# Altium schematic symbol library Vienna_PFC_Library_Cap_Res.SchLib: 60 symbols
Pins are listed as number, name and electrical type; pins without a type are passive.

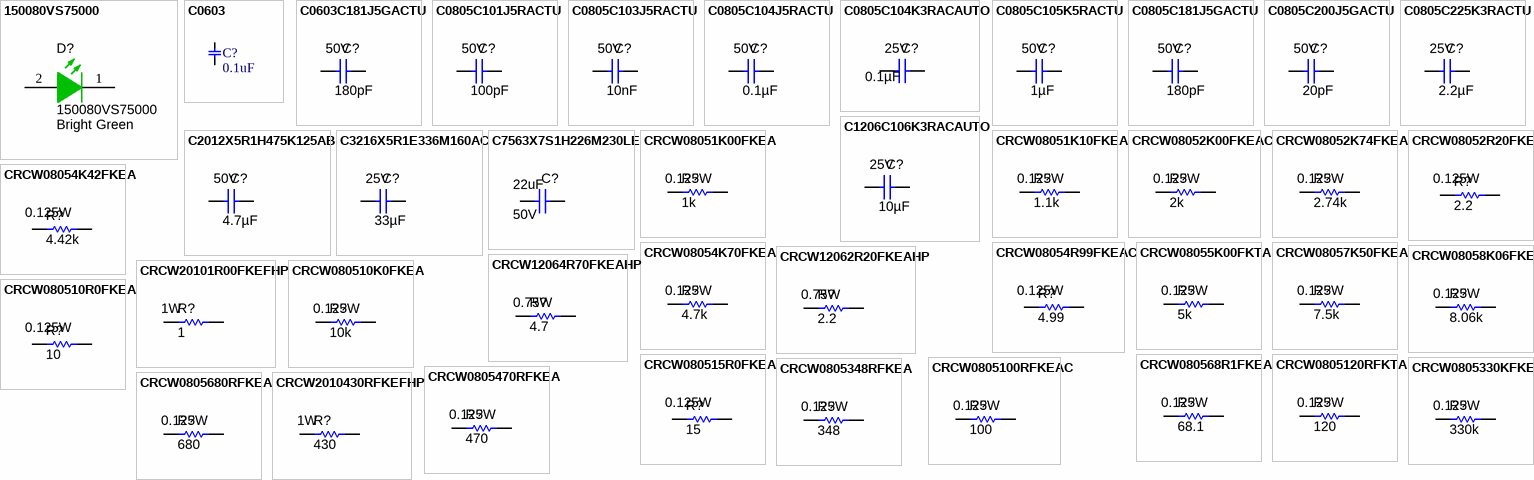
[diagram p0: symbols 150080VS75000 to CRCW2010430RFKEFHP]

## 150080VS75000
designator D?  value Bright Green
LED, Bright Green, SMD; Manufacturer: Wurth Elektronik; SymbolCreator: Altium; Type: AlInGaP; Vf_V: 2; Value2: 2V; Io_A: 0.02; Vr_V: 5; Tjmax_C: 85; Power_TotalModule: 0.072; Value1: 0.072W; Angle: 140; U/M: EA
footprint WL-SMCW_Green_0805 (SMD, 2-Leads, Body 2x1.25mm)
pins: 1 K, 2 A

## C0603
designator C?, comment 0.1uF
footprint C0603
pins: 1, 2

## C0603C181J5GACTU
designator C?  VDC_V: 50V  ValueDisplayed: 180pF  (hidden comment: C0603C181J5GACTU)
CAP, CERM, 180 pF, 50 V, +/- 5%, C0G/NP0, 0603; Manufacturer: Kemet; Polarized: N; CompType: Capacitor; Value: 180pF; U/M: EA; Cap_F: 0.00000000018; Tolerance_%: 5; Value1: Unknown; TaMin_C: -55; TaMax_C: 125; Cap_Case: 0603; SizeArea_mm2: 1.28; SizeAreaWB_mm2: 4.68; SizeX_mm: 1.6; SizeY_mm: 0.8; SizeZ_mm: 1; AEC Category: Q200
signal-integrity model Cap
simulation model Cap
footprint 0603 (0603 from SM-752 data)
footprint 0603M
footprint 0603L
footprint 0603_HV
footprint 0603S
pins: 1, 2

## C0805C101J5RACTU
designator C?  VDC_V: 50V  ValueDisplayed: 100pF  (hidden comment: C0805C101J5RACTU)
CAP, CERM, 100 pF, 50 V, +/- 5%, X7R, 0805; Manufacturer: Kemet; CompType: Capacitor; Tolerance_%: 5; TaMin_C: -55; TaMax_C: 125; Cap_Case: 0805; AEC Category: Q200
signal-integrity model Cap
simulation model Cap
footprint 0805_HV (0805 with 30mil clearance between pads)
footprint 0805_HV1
footprint 0805
footprint 0805M
footprint 0805L
pins: 1, 2

## C0805C103J5RACTU
designator C?  VDC_V: 50V  ValueDisplayed: 10nF  (hidden comment: C0805C103J5RACTU)
CAP, CERM, 10 nF, 50 V, +/- 5%, X7R, 0805; Manufacturer: Kemet; CompType: Capacitor; Tolerance_%: 5; TaMin_C: -55; TaMax_C: 125; Cap_Case: 0805; AEC Category: Q200
signal-integrity model Cap
simulation model Cap
footprint 0805_HV (0805 with 30mil clearance between pads)
footprint 0805_HV1
footprint 0805
footprint 0805M
footprint 0805L
pins: 1, 2

## C0805C104J5RACTU
designator C?  VDC_V: 50V  ValueDisplayed: 0.1µF  (hidden comment: C0805C104J5RACTU)
CAP, CERM, 0.1 µF, 50 V, +/- 5%, X7R, 0805; Manufacturer: Kemet; CompType: Capacitor; Tolerance_%: 5; TaMin_C: -55; TaMax_C: 125; Cap_Case: 0805; AEC Category: Q200
signal-integrity model Cap
simulation model Cap
footprint 0805_HV (0805 with 30mil clearance between pads)
footprint 0805_HV1
footprint 0805
footprint 0805M
footprint 0805L
pins: 1, 2

## C0805C104K3RACAUTO
designator C?  VDC_V: 25V  ValueDisplayed: 0.1µF  (hidden comment: C0805C104K3RACAUTO)
CAP, CERM, 0.1 µF, 25 V, +/- 10%, X7R, 0805; Manufacturer: Kemet; Polarized: N; CompType: Capacitor; Value: 0.1uF; U/M: EA; Cap_F: 0.0000001; Tolerance_%: 10; ESR_ohm: 0.064; Value1: 0.064 ohm; IRMS_A: 1.64; TaMin_C: -55; TaMax_C: 125; Cap_Case: 0805; AEC Category: Q200
signal-integrity model Cap
simulation model Cap
footprint 0805_HV
footprint 0805_HV1
footprint 0805
footprint 0805M
footprint 0805L
pins: 1, 2

## C0805C105K5RACTU
designator C?  VDC_V: 50V  ValueDisplayed: 1µF  (hidden comment: C0805C105K5RACTU)
CAP, CERM, 1 µF, 50 V, +/- 5%, X7R, 0805; Manufacturer: Kemet; CompType: Capacitor; Tolerance_%: 10; TaMin_C: -55; TaMax_C: 125; Cap_Case: 0805; AEC Category: Q200
signal-integrity model Cap
simulation model Cap
footprint 0805_HV (0805 with 30mil clearance between pads)
footprint 0805_HV1
footprint 0805
footprint 0805M
footprint 0805L
pins: 1, 2

## C0805C181J5GACTU
designator C?  VDC_V: 50V  ValueDisplayed: 180pF  (hidden comment: C0805C181J5GACTU)
CAP, CERM, 180 pF, 50 V, +/- 5%, X7R, 0805; Manufacturer: Kemet; CompType: Capacitor; Tolerance_%: 5; TaMin_C: -55; TaMax_C: 125; Cap_Case: 0805; AEC Category: Q200
signal-integrity model Cap
simulation model Cap
footprint 0805_HV (0805 with 30mil clearance between pads)
footprint 0805_HV1
footprint 0805
footprint 0805M
footprint 0805L
pins: 1, 2

## C0805C200J5GACTU
designator C?, comment VDC_V: 50V  ValueDisplayed: 20pF  (hidden comment: C0805C101J5RACTU)
CAP, CERM, 20 pF, 50 V, +/- 5%, X7R, 0805; Manufacturer: Kemet; CompType: Capacitor; Tolerance_%: 5; TaMin_C: -55; TaMax_C: 125; Cap_Case: 0805; AEC Category: Q200
signal-integrity model Cap
simulation model Cap
footprint 0805_HV (0805 with 30mil clearance between pads)
footprint 0805_HV1
footprint 0805
footprint 0805M
footprint 0805L
pins: 1, 2

## C0805C225K3RACTU
designator C?  VDC_V: 25V  ValueDisplayed: 2.2µF  (hidden comment: C0805C225K3RACTU)
CAP, CERM, 2.2 µF, 25 V, +/- 5%, X7R, 0805; Manufacturer: Kemet; CompType: Capacitor; Tolerance_%: 10; TaMin_C: -55; TaMax_C: 125; Cap_Case: 0805; AEC Category: Q200
signal-integrity model Cap
simulation model Cap
footprint 0805_HV (0805 with 30mil clearance between pads)
footprint 0805_HV1
footprint 0805
footprint 0805M
footprint 0805L
pins: 1, 2

## C1206C106K3RACAUTO
designator C?  VDC_V: 25V  ValueDisplayed: 10µF  (hidden comment: C1206C106K3RACAUTO)
CAP, CERM, 10 µF, 25 V, +/- 10%, X7R, 1206_190; Manufacturer: Kemet; Polarized: N; CompType: Capacitor; Value: 10uF; U/M: EA; Cap_F: 0.00001; Tolerance_%: 10; Value1: Unknown; TaMin_C: -55; TaMax_C: 125; Cap_Case: 1206; AEC Category: Q200
signal-integrity model Cap
simulation model Cap
footprint 1206_190
footprint 1206_190M
footprint 1206_190L
pins: 1, 2

## C2012X5R1H475K125AB
designator C?  VDC_V: 50V  ValueDisplayed: 4.7µF  (hidden comment: C2012X5R1H475K125AB)
CAP, CERM, 4.7 µF, 50 V, +/- 10%, X5R, 0805; Manufacturer: TDK; Polarized: N; CompType: Capacitor; Value: 4.7uF; U/M: EA; Cap_F: 0.0000047; Tolerance_%: 10; Value1: Unknown; TaMin_C: -55; TaMax_C: 85; Cap_Case: 0805; AEC Category: Q200
signal-integrity model Cap
simulation model Cap
footprint 0805_HV (0805 with 30mil clearance between pads)
pins: 1, 2

## C3216X5R1E336M160AC
designator C?  VDC_V: 25V  ValueDisplayed: 33µF  (hidden comment: C3216X5R1E336M160AC)
CAP, CERM, 33 µF, 25 V, +/- 20%, X5R, 1206; Manufacturer: TDK; Polarized: N; CompType: Capacitor; Value: 33uF; U/M: EA; Tolerance_%: 20; Value1: Unknown; TaMin_C: -55; TaMax_C: 85; Cap_Case: 1206; AEC Category: Q200
signal-integrity model Cap
simulation model Cap
footprint 1206_190
pins: 1, 2

## C7563X7S1H226M230LE
designator C?  value 22uF  VDC_V: 50V  (hidden comment: C7563X7S1H226M230LE)
CAP, CERM, 22 µF, 50V, +/- 20%, X7S, 3525; AEC Category: Q200; ValueDisplayed: 22µF
signal-integrity model Cap
simulation model Cap
footprint 3025 (Chip Resistor, Body 7.5*6.3mm, IPC Medium Density)
pins: 1, 2

## CRCW08051K00FKEA
designator R?  Value2: 0.125W  ValueDisplayed: 1k  (hidden comment: CRCW08051K00FKEA)
RES, 1 k, 1%, 0.125 W, 0805; Manufacturer: Vishay-Dale; CompType: Resistor; Value: 1k; Value_Code: 1kR; Tolerance_%: 1; Power_W: 0.125; VDC_V: 150; TempCo: 100 ppm/C; EIA_Code: E96; U/M: EA; AEC Category: Q200
signal-integrity model Resistor
simulation model Resistor
footprint 0805_HV (0805 with 30mil clearance between pads)
footprint 0805_HV1
footprint 0805
footprint 0805M
pins: 1, 2

## CRCW08051K10FKEA
designator R?  Value2: 0.125W  ValueDisplayed: 1.1k  (hidden comment: CRCW08051K10FKEA)
RES, 1.1K, 1%, 0.125 W, 0805; Manufacturer: Vishay-Dale; CompType: Resistor; Tolerance_%: 1; Power_W: 0.125; VDC_V: 150; TempCo: 100 ppm/C; EIA_Code: E96; U/M: EA; AEC Category: Q200
signal-integrity model Resistor
simulation model Resistor
footprint 0805_HV (0805 with 30mil clearance between pads)
footprint 0805_HV1
footprint 0805
footprint 0805M
pins: 1, 2

## CRCW08052K00FKEAC
designator R?  Value2: 0.125W  ValueDisplayed: 2k  (hidden comment: CRCW08052K00FKEAC)
RES, 2K, 1%, 0.125 W, 0805; Manufacturer: Vishay-Dale; CompType: Resistor; Value: 348; Tolerance_%: 1; Power_W: 0.125; VDC_V: 150; TempCo: 100 ppm/C; EIA_Code: E96; U/M: EA; AEC Category: Q200
signal-integrity model Resistor
simulation model Resistor
footprint 0805_HV (0805 with 30mil clearance between pads)
footprint 0805_HV1
footprint 0805
footprint 0805M
pins: 1, 2

## CRCW08052K74FKEA
designator R?  Value2: 0.125W  ValueDisplayed: 2.74k  (hidden comment: CRCW08052K74FKEA)
RES, 2.74K, 1%, 0.125 W, 0805; Manufacturer: Vishay-Dale; CompType: Resistor; Res_ohm: 348; Tolerance_%: 1; Power_W: 0.125; VDC_V: 150; TempCo: 100 ppm/C; EIA_Code: E96; U/M: EA; AEC Category: Q200
signal-integrity model Resistor
simulation model Resistor
footprint 0805_HV (0805 with 30mil clearance between pads)
footprint 0805_HV1
footprint 0805
footprint 0805M
pins: 1, 2

## CRCW08052R20FKEA
designator R?  Value2: 0.125W  ValueDisplayed: 2.2  (hidden comment: CRCW08052R20FKEA)
RES, 2.2 1%, 0.125 W, 0805; Manufacturer: Vishay-Dale; CompType: Resistor; Value: 2.2; Value_Code: 2R2; Tolerance_%: 1; Power_W: 0.125; VDC_V: 150; TempCo: 100 ppm/C; SizeArea_mm2: 2.5; SizeX_mm: 2; SizeY_mm: 1.25; SizeZ_mm: 1.45; EIA_Code: E24; U/M: EA; AEC Category: Q200
signal-integrity model Resistor
simulation model Resistor
footprint 0805_HV (0805 with 30mil clearance between pads)
footprint 0805_HV1
footprint 0805
footprint 0805M
footprint 0805L
pins: 1, 2

## CRCW08054K42FKEA
designator R?  Value2: 0.125W  ValueDisplayed: 4.42k  (hidden comment: CRCW08054K42FKEA)
RES, 4.42k 1%, 0.125 W, 0805; Manufacturer: Vishay-Dale; CompType: Resistor; Value_Code: 4K42; Tolerance_%: 1; Power_W: 0.125; VDC_V: 150; TempCo: 100 ppm/C; SizeArea_mm2: 2.5; SizeX_mm: 2; SizeY_mm: 1.25; SizeZ_mm: 1.45; EIA_Code: E24; U/M: EA; AEC Category: Q200
signal-integrity model Resistor
simulation model Resistor
footprint 0805_HV (0805 with 30mil clearance between pads)
footprint 0805_HV1
footprint 0805
footprint 0805M
footprint 0805L
pins: 1, 2

## CRCW08054K70FKEA
designator R?  Value2: 0.125W  ValueDisplayed: 4.7k  (hidden comment: CRCW08054K70FKEA)
RES, 4.7K, 1%, 0.125 W, 0805; Manufacturer: Vishay-Dale; CompType: Resistor; Tolerance_%: 1; Power_W: 0.125; VDC_V: 150; TempCo: 100 ppm/C; EIA_Code: E96; U/M: EA; AEC Category: Q200
signal-integrity model Resistor
simulation model Resistor
footprint 0805_HV (0805 with 30mil clearance between pads)
footprint 0805_HV1
footprint 0805
footprint 0805M
pins: 1, 2

## CRCW08054R99FKEAC
designator R?  Value2: 0.125W  ValueDisplayed: 4.99  (hidden comment: CRCW08054R99FKEAC)
RES, 4.99 1%, 0.125 W, 0805; Manufacturer: Vishay-Dale; CompType: Resistor; Value: 4.99; Value_Code: 4R99; Tolerance_%: 1; Power_W: 0.125; VDC_V: 150; TempCo: 100 ppm/C; SizeArea_mm2: 2.5; SizeX_mm: 2; SizeY_mm: 1.25; SizeZ_mm: 1.45; EIA_Code: E24; U/M: EA; AEC Category: Q200
signal-integrity model Resistor
simulation model Resistor
footprint 0805_HV (0805 with 30mil clearance between pads)
footprint 0805_HV1
footprint 0805
footprint 0805M
footprint 0805L
pins: 1, 2

## CRCW08055K00FKTA
designator R?  Value2: 0.125W  ValueDisplayed: 5k  (hidden comment: CRCW08055K00FKTA)
RES, 5K, 1%, 0.125 W, 0805; Manufacturer: Vishay-Dale; CompType: Resistor; Tolerance_%: 1; Power_W: 0.125; VDC_V: 150; TempCo: 100 ppm/C; EIA_Code: E96; U/M: EA; AEC Category: Q200
signal-integrity model Resistor
simulation model Resistor
footprint 0805_HV (0805 with 30mil clearance between pads)
footprint 0805_HV1
footprint 0805
footprint 0805M
pins: 1, 2

## CRCW08057K50FKEA
designator R?  Value2: 0.125W  ValueDisplayed: 7.5k  (hidden comment: CRCW08057K50FKEA)
RES, 7.5K, 1%, 0.125 W, 0805; Manufacturer: Vishay-Dale; CompType: Resistor; Value: 348; Tolerance_%: 1; Power_W: 0.125; VDC_V: 150; TempCo: 100 ppm/C; EIA_Code: E96; U/M: EA; AEC Category: Q200
signal-integrity model Resistor
simulation model Resistor
footprint 0805_HV (0805 with 30mil clearance between pads)
footprint 0805_HV1
footprint 0805
footprint 0805M
pins: 1, 2

## CRCW08058K06FKEA
designator R?  Value2: 0.125W  ValueDisplayed: 8.06k  (hidden comment: CRCW08058K06FKEA)
RES, 8.06K, 1%, 0.125 W, 0805; Manufacturer: Vishay-Dale; CompType: Resistor; Value: 348; Tolerance_%: 1; Power_W: 0.125; VDC_V: 150; TempCo: 100 ppm/C; EIA_Code: E96; U/M: EA; AEC Category: Q200
signal-integrity model Resistor
simulation model Resistor
footprint 0805_HV (0805 with 30mil clearance between pads)
footprint 0805_HV1
footprint 0805
footprint 0805M
pins: 1, 2

## CRCW12062R20FKEAHP
designator R?, comment Value2: 0.75W  ValueDisplayed: 2.2  (hidden comment: CRCW12064R70FKEAHP)
RES, 2.2, 1%, 0.75 W, 1206; Manufacturer: Vishay-Dale; CompType: Resistor; Value: 2.2; Value_Code: 2R2; Tolerance_%: 1; Power_W: 0.75; VDC_V: 200V; TempCo: 100 ppm/C; U/M: EA; AEC Category: Q200
signal-integrity model Resistor
simulation model Resistor
footprint 1206_190
footprint 0805_HV1
footprint 0805
footprint 0805M
pins: 1, 2

## CRCW12064R70FKEAHP
designator R?, comment Value2: 0.75W  ValueDisplayed: 4.7  (hidden comment: CRCW12062R20FKEAHP)
RES, 4.7, 1%, 0.75 W, 1206; Manufacturer: Vishay-Dale; CompType: Resistor; Value: 4.7; Value_Code: 4R7; Tolerance_%: 1; Power_W: 0.75; VDC_V: 200V; TempCo: 100 ppm/C; U/M: EA; AEC Category: Q200
signal-integrity model Resistor
simulation model Resistor
footprint 1206_190
footprint 0805_HV1
footprint 0805
footprint 0805M
pins: 1, 2

## CRCW20101R00FKEFHP
designator R?  Value2: 1W  ValueDisplayed: 1  (hidden comment: CRCW20101R00FKEFHP)
RES, 1, 1%, 1 W, 2010; Manufacturer: Vishay-Dale; CompType: Resistor; Value: 1; Value_Code: 1R; VDC_V: 300; TempCo: 100 ppm/C; U/M: EA; AEC Category: Q200
signal-integrity model Resistor
simulation model Resistor
footprint 2010 (Chip Capacitor, Body 5.08x2.54mm, IPC Medium Density)
footprint 0805_HV1
footprint 0805
footprint 0805M
pins: 1, 2

## CRCW080510K0FKEA
designator R?  Value2: 0.125W  ValueDisplayed: 10k  (hidden comment: CRCW080510K0FKEA)
RES, 10K, 1%, 0.125 W, 0805; Manufacturer: Vishay-Dale; CompType: Resistor; Tolerance_%: 1; Power_W: 0.125; VDC_V: 150; TempCo: 100 ppm/C; EIA_Code: E96; U/M: EA; AEC Category: Q200
signal-integrity model Resistor
simulation model Resistor
footprint 0805_HV (0805 with 30mil clearance between pads)
footprint 0805_HV1
footprint 0805
footprint 0805M
pins: 1, 2

## CRCW080510R0FKEA
designator R?, comment Value2: 0.125W  ValueDisplayed: 10  (hidden comment: CRCW080510R0JNEA)
RES, 10, 1%, 0.125 W, 0805; Manufacturer: Vishay-Dale; CompType: Resistor; Value: 10; Value_Code: 10R0; Tolerance_%: 1; Power_W: 0.125; VDC_V: 150; TempCo: 100 ppm/C; SizeArea_mm2: 2.5; SizeX_mm: 2; SizeY_mm: 1.25; SizeZ_mm: 1.45; EIA_Code: E24; U/M: EA; AEC Category: Q200
signal-integrity model Resistor
simulation model Resistor
footprint 0805_HV (0805 with 30mil clearance between pads)
footprint 0805_HV1
footprint 0805
footprint 0805M
footprint 0805L
pins: 1, 2

## CRCW080515R0FKEA
designator R?  Value2: 0.125W  ValueDisplayed: 15  (hidden comment: CRCW080515R0FKEA)
RES, 15, 1%, 0.125 W, 0805; Manufacturer: Vishay-Dale; CompType: Resistor; Value: 15; Value_Code: 15R0; Tolerance_%: 1; Power_W: 0.125; VDC_V: 150; TempCo: 100 ppm/C; SizeArea_mm2: 2.5; SizeX_mm: 2; SizeY_mm: 1.25; SizeZ_mm: 1.45; EIA_Code: E24; U/M: EA; AEC Category: Q200
signal-integrity model Resistor
simulation model Resistor
footprint 0805_HV (0805 with 30mil clearance between pads)
footprint 0805_HV1
footprint 0805
footprint 0805M
footprint 0805L
pins: 1, 2

## CRCW080568R1FKEA
designator R?  Value2: 0.125W  ValueDisplayed: 68.1  (hidden comment: CRCW080568R1FKEA)
RES, 68.1, 1%, 0.125 W, 0805; Manufacturer: Vishay-Dale; CompType: Resistor; Value: 348; Value_Code: 68R1; Tolerance_%: 1; Power_W: 0.125; VDC_V: 150; TempCo: 100 ppm/C; EIA_Code: E96; U/M: EA; AEC Category: Q200
signal-integrity model Resistor
simulation model Resistor
footprint 0805_HV (0805 with 30mil clearance between pads)
footprint 0805_HV1
footprint 0805
footprint 0805M
pins: 1, 2

## CRCW0805100RFKEAC
designator R?  Value2: 0.125W  ValueDisplayed: 100  (hidden comment: CRCW0805100RFKEAC)
RES, 100, 1%, 0.125 W, 0805; Manufacturer: Vishay-Dale; CompType: Resistor; Value: 100; Value_Code: 100R; Tolerance_%: 1; Power_W: 0.125; VDC_V: 150; TempCo: 100 ppm/C; EIA_Code: E96; U/M: EA; AEC Category: Q200
signal-integrity model Resistor
simulation model Resistor
footprint 0805_HV (0805 with 30mil clearance between pads)
footprint 0805_HV1
footprint 0805
footprint 0805M
pins: 1, 2

## CRCW0805120RFKTA
designator R?  Value2: 0.125W  ValueDisplayed: 120  (hidden comment: CRCW0805120RFKTA)
RES, 120, 1%, 0.125 W, 0805; Manufacturer: Vishay-Dale; CompType: Resistor; Value: 120; Value_Code: 120R; Tolerance_%: 1; Power_W: 0.125; VDC_V: 150; TempCo: 100 ppm/C; EIA_Code: E96; U/M: EA; AEC Category: Q200
signal-integrity model Resistor
simulation model Resistor
footprint 0805_HV (0805 with 30mil clearance between pads)
footprint 0805_HV1
footprint 0805
footprint 0805M
pins: 1, 2

## CRCW0805330KFKEA
designator R?  Value2: 0.125W  ValueDisplayed: 330k  (hidden comment: CRCW0805330KFKEA)
RES, 330 k, 1%, 0.125 W, 0805; Manufacturer: Vishay-Dale; CompType: Resistor; Value: 330k; Value_Code: 330kR; Tolerance_%: 1; Power_W: 0.125; VDC_V: 150; TempCo: 100 ppm/C; EIA_Code: E96; U/M: EA; AEC Category: Q200
signal-integrity model Resistor
simulation model Resistor
footprint 0805_HV (0805 with 30mil clearance between pads)
footprint 0805_HV1
footprint 0805
footprint 0805M
pins: 1, 2

## CRCW0805348RFKEA
designator R?  Value2: 0.125W  ValueDisplayed: 348  (hidden comment: CRCW0805348RFKEA)
RES, 348, 1%, 0.125 W, 0805; Manufacturer: Vishay-Dale; CompType: Resistor; Value: 348; Value_Code: 348R; Tolerance_%: 1; Power_W: 0.125; VDC_V: 150; TempCo: 100 ppm/C; EIA_Code: E96; U/M: EA; AEC Category: Q200
signal-integrity model Resistor
simulation model Resistor
footprint 0805_HV (0805 with 30mil clearance between pads)
footprint 0805_HV1
footprint 0805
footprint 0805M
pins: 1, 2

## CRCW0805470RFKEA
designator R?  Value2: 0.125W  ValueDisplayed: 470  (hidden comment: CRCW0805470RFKEA)
RES, 470, 1%, 0.125 W, 0805; Manufacturer: Vishay-Dale; CompType: Resistor; Value: 470; Value_Code: 470R; Tolerance_%: 1; Power_W: 0.125; VDC_V: 150; TempCo: 100 ppm/C; U/M: EA; AEC Category: Q200
signal-integrity model Resistor
simulation model Resistor
footprint 0805_HV (0805 with 30mil clearance between pads)
footprint 0805_HV1
footprint 0805
footprint 0805M
pins: 1, 2

## CRCW0805680RFKEA
designator R?  Value2: 0.125W  ValueDisplayed: 680  (hidden comment: CRCW0805680RFKEA)
RES, 680, 1%, 0.125 W, 0805; Manufacturer: Vishay-Dale; CompType: Resistor; Value: 680; Value_Code: 680R; Tolerance_%: 1; Power_W: 0.125; VDC_V: 150; TempCo: 100 ppm/C; EIA_Code: E96; U/M: EA; AEC Category: Q200
signal-integrity model Resistor
simulation model Resistor
footprint 0805_HV (0805 with 30mil clearance between pads)
footprint 0805_HV1
footprint 0805
footprint 0805M
pins: 1, 2

## CRCW2010430RFKEFHP
designator R?, comment Value2: 1W  ValueDisplayed: 430  (hidden comment: CRCW20101R00FKEFHP)
RES, 430, 1%, 1 W, 2010; Manufacturer: Vishay-Dale; CompType: Resistor; Value: 430; Res_ohm: 1; Value_Code: 430R; VDC_V: 300; TempCo: 100 ppm/C; U/M: EA; AEC Category: Q200
signal-integrity model Resistor
simulation model Resistor
footprint 2010 (Chip Capacitor, Body 5.08x2.54mm, IPC Medium Density)
footprint 0805_HV1
footprint 0805
footprint 0805M
pins: 1, 2

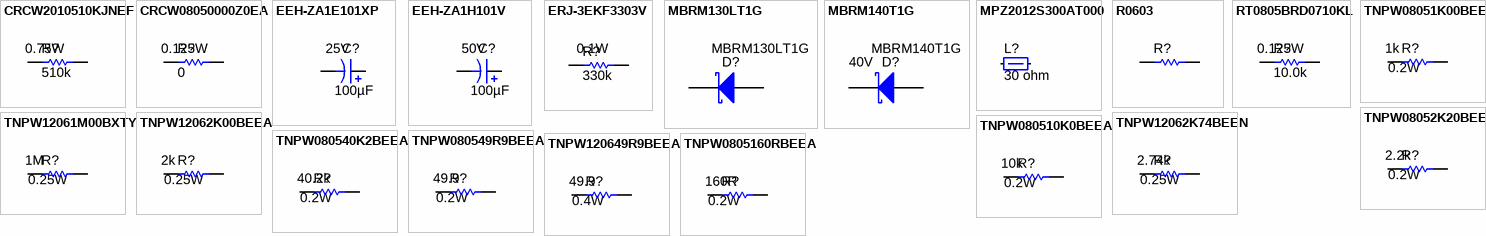
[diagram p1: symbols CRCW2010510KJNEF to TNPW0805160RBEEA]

## CRCW2010510KJNEF
designator R?  Value2: 0.75W  ValueDisplayed: 510k  (hidden comment: CRCW2010510KJNEF)
RES, 510 k, 5%, 0.75 W, AEC-Q200 Grade 0, 2010; Manufacturer: Vishay-Dale; CompType: Resistor; Value: 510k; Res_ohm: 510000; Tolerance_%: 5; Power_W: 0.75; VDC_V: 400; TempCo: 200 ppm/C; SizeArea_mm2: 12.5; SizeY_mm: 2.5; SizeZ_mm: 1.66; EIA_Code: E24; U/M: EA; AEC Category: Q200; AEC Qualified: Y; AEC Grade: 0
signal-integrity model Resistor
simulation model Resistor
footprint 2010 (Chip Capacitor, Body 5.08x2.54mm, IPC Medium Density)
footprint 2010M
footprint 2010L
pins: 1, 2

## CRCW08050000Z0EA
designator R?  Value2: 0.125W  ValueDisplayed: 0  (hidden comment: CRCW08050000Z0EA)
RES, 0, 5%, 0.125 W, 0805; Manufacturer: Vishay-Dale; CompType: Resistor; Value: 0; Tolerance_%: 5; Power_W: 0.125; VDC_V: 150; TempCo: 200 ppm/C; EIA_Code: E24; U/M: EA; AEC Category: Q200
signal-integrity model Resistor
simulation model Resistor
footprint 0805_HV (0805 with 30mil clearance between pads)
pins: 1, 2

## EEH-ZA1E101XP
designator C?  VDC_V: 25V  ValueDisplayed: 100µF  (hidden comment: EEH-ZA1E101XP)
CAP, Polymer Hybrid, 100 µF, 25 V, +/- 20%, 30 ohm, 6.3x7.7 SMD; Manufacturer: Panasonic; Polarized: Y; CompType: Capacitor; Value: 100uF; U/M: EA; Cap_F: 0.0001; Tolerance_%: 20; Value1: 30 ohm; ESR_ohm: 30; IRMS_A: 2; TaMin_C: -55; TaMax_C: 105; AEC Category: Q200
signal-integrity model Cap
simulation model Cap
footprint SM_RADIAL_6.3BMM (Nichicon 6.3x7.7)
pins: 1 +, 2 -

## EEH-ZA1H101V
designator C?  VDC_V: 50V  ValueDisplayed: 100µF  (hidden comment: EEH-ZA1H101V)
CAP, Polymer Hybrid, 100 µF, 50 V, +/- 20%, 30 ohm, 6.3x7.7 SMD; Manufacturer: Panasonic; Polarized: Y; CompType: Capacitor; Value: 100uF; U/M: EA; Cap_F: 0.0001; Tolerance_%: 20; Value1: 30 ohm; ESR_ohm: 30; IRMS_A: 2; TaMin_C: -55; TaMax_C: 105; AEC Category: Q200
signal-integrity model Cap
simulation model Cap
footprint SM_RADIAL_10BMM (Nichicon 10x10.5)
pins: 1 +, 2 -

## ERJ-3EKF3303V
designator R?  Value2: 0.1W  ValueDisplayed: 330k  (hidden comment: ERJ-3EKF3303V)
RES, 330 k, 1%, 0.1 W, AEC-Q200 Grade 0, 0603; Manufacturer: Panasonic; CompType: Resistor; Value: 330k; Res_ohm: 330000; Tolerance_%: 1; Power_W: 0.1; VDC_V: 75; TempCo: 100 ppm/C; SizeArea_mm2: 1.28; SizeX_mm: 1.6; SizeY_mm: 0.8; U/M: EA; AEC Category: Q200; AEC Qualified: Y; AEC Grade: 0
signal-integrity model Resistor
simulation model Resistor
footprint 0603
footprint 0603M
footprint 0603L
footprint 0603_HV
footprint 0603S
pins: 1, 2

## MBRM130LT1G
designator D?
Diode, Schottky, 30 V, 1 A, POWERMITE; Manufacturer: ON Semiconductor; U/M: EA; Vf_V: 0.38; Value: 30V; Value1: 1A; Value2: 0.38V; Io_A: 1; Vr_V: 30; TJmax_C: 125; AEC Category: Q101
signal-integrity model Diode
footprint MBRM-POWERMITE (On Semi recommended land pattern, 457-04.pdf Rev 04E dated 2008-11-26)
pins: 1 K, 2 A

## MBRM140T1G
designator D?  value 40V
Diode, Schottky, 40 V, 1 A, POWERMITE; Manufacturer: ON Semiconductor; U/M: EA; Vf_V: 0.55; Value1: 1A; Value2: 0.55V; Io_A: 1; Vr_V: 40; TJmax_C: 125; AEC Category: Q101
signal-integrity model Diode
footprint MBRM-POWERMITE (On Semi recommended land pattern, 457-04.pdf Rev 04E dated 2008-11-26)
pins: 1 K, 2 A

## MPZ2012S300AT000
designator L?  value 30 ohm  (hidden comment: MPZ2012S300AT000)
Ferrite Bead, 30 ohm @ 100 MHz, 6 A, 0805; Manufacturer: TDK; Imax_A: 6; DCR_ohm: 0.01; Value1: 0.01 ohm; Value2: 6A; ZTyp@100MHz_Ohm: 30
footprint 0805_HV (0805 with 30mil clearance between pads)
footprint 0805_HV1
footprint 0805
footprint 0805M
footprint 0805L
pins: 1, 2

## R0603
designator R?
CompType: Resistor
signal-integrity model Resistor
simulation model Resistor
footprint 2010 (Chip Capacitor, Body 5.08x2.54mm, IPC Medium Density)
footprint 2010M
footprint 2010L
footprint R0603
pins: 1, 2

## RT0805BRD0710KL
designator R?  Value2: 0.125W  ValueDisplayed: 10.0k  (hidden comment: RT0805BRD0710KL)
RES, 10.0 k, 0.1%, 0.125 W, 0805; Manufacturer: Yageo America; CompType: Resistor; Value: 10.0k; Res_ohm: 10000; Value_Code: 10k0; Tolerance_%: 0.1; Power_W: 0.125; VDC_V: 150; TempCo: 25 ppm/C; EIA_Code: E192; U/M: EA; AEC Category: Q200
signal-integrity model Resistor
simulation model Resistor
footprint 0805_HV
footprint 0805_HV1
footprint 0805_HV (0805 with 30mil clearance between pads)
footprint 0805M
pins: 1, 2

## TNPW08051K00BEEA
designator R?, comment value 1k  Power_W: 0.2W  (hidden comment: TNPW080510K0BEEA)
RES 1K OHM 0.1% 1/5W 0805; Manufacturer: Vishay; CompType: Resistor; Tolerance_%: 0.1; VDC_V: 200V; TempCo: 25ppm/C; AEC Category: Q200
signal-integrity model Resistor
simulation model Resistor
footprint 0805_HV (0805 with 30mil clearance between pads)
footprint 2010M
footprint 2010L
pins: 1, 2

## TNPW08052K20BEEA
designator R?  value 2.2k  Power_W: 0.2W  (hidden comment: TNPW08052K20BEEA)
RES 2.2K OHM 0.1% 1/5W 0805; Manufacturer: Vishay; CompType: Resistor; Tolerance_%: 0.1; VDC_V: 200V; TempCo: 25ppm/C; AEC Category: Q200
signal-integrity model Resistor
simulation model Resistor
footprint 0805_HV (0805 with 30mil clearance between pads)
footprint 2010M
footprint 2010L
pins: 1, 2

## TNPW12061M00BXTY
designator R?  value 1M  Power_W: 0.25W  (hidden comment: TNPW12061M00BXTY)
RES, 1 M, 0.1%, 0.25 W, 15 PPM / C, AEC-Q200; Manufacturer: Vishay; CompType: Resistor; Tolerance_%: 0.1; VDC_V: 200V; AEC Category: Q200
signal-integrity model Resistor
simulation model Resistor
footprint 1206_190
footprint 2010M
footprint 2010L
pins: 1, 2

## TNPW12062K00BEEA
designator R?  value 2k  Power_W: 0.25W  (hidden comment: TNPW12062K00BEEA)
RES, 2 k,  0.1%, 0.25 W, 25 PPM / C, AEC-Q200; Manufacturer: Vishay; CompType: Resistor; Tolerance_%: 0.1; VDC_V: 200V; AEC Category: Q200
signal-integrity model Resistor
simulation model Resistor
footprint 1206_190
footprint 2010M
footprint 2010L
pins: 1, 2

## TNPW12062K74BEEN
designator R?  value 2.74k  Power_W: 0.25W  (hidden comment: TNPW12062K74BEEN)
RES, 2.74 k,  0.1%, 0.25 W, 25 PPM / C, AEC-Q200; Manufacturer: Vishay; CompType: Resistor; Tolerance_%: 0.1; VDC_V: 200V; AEC Category: Q200
signal-integrity model Resistor
simulation model Resistor
footprint 1206_190
footprint 2010M
footprint 2010L
pins: 1, 2

## TNPW080510K0BEEA
designator R?  value 10k  Power_W: 0.2W  (hidden comment: TNPW080510K0BEEA)
RES 10K OHM 0.1% 1/5W 0805; Manufacturer: Vishay; CompType: Resistor; Tolerance_%: 0.1; VDC_V: 200V; TempCo: 25ppm/C; AEC Category: Q200
signal-integrity model Resistor
simulation model Resistor
footprint 0805_HV (0805 with 30mil clearance between pads)
footprint 2010M
footprint 2010L
pins: 1, 2

## TNPW080540K2BEEA
designator R?  value 40.2k  Power_W: 0.2W  (hidden comment: TNPW080540K2BEEA)
RES 40.2K OHM 0.1% 1/5W 0805; Manufacturer: Vishay; CompType: Resistor; Tolerance_%: 0.1; VDC_V: 200V; TempCo: 25ppm/C; AEC Category: Q200
signal-integrity model Resistor
simulation model Resistor
footprint 0805_HV (0805 with 30mil clearance between pads)
footprint 2010M
footprint 2010L
pins: 1, 2

## TNPW080549R9BEEA
designator R?  value 49.9  Power_W: 0.2W  (hidden comment: TNPW080549R9BEEA)
RES 49.9 OHM 0.1% 1/5W 0805; Manufacturer: Vishay; CompType: Resistor; Tolerance_%: 0.1; VDC_V: 200V; TempCo: 25ppm/C; AEC Category: Q200
signal-integrity model Resistor
simulation model Resistor
footprint 0805_HV (0805 with 30mil clearance between pads)
footprint 2010M
footprint 2010L
pins: 1, 2

## TNPW120649R9BEEA
designator R?  value 49.9  Power_W: 0.4W  (hidden comment: TNPW120649R9BEEA)
RES, 49.9  0.1%, 0.4 W, 25 PPM / C, AEC-Q200; Manufacturer: Vishay; CompType: Resistor; Tolerance_%: 0.1; VDC_V: 200V; AEC Category: Q200
signal-integrity model Resistor
simulation model Resistor
footprint 1206_190
footprint 2010M
footprint 2010L
pins: 1, 2

## TNPW0805160RBEEA
designator R?  value 160R  Power_W: 0.2W  (hidden comment: TNPW0805160RBEEA)
RES 160R OHM 0.1% 1/5W 0805; Manufacturer: Vishay; CompType: Resistor; Tolerance_%: 0.1; VDC_V: 200V; TempCo: 25ppm/C; AEC Category: Q200
signal-integrity model Resistor
simulation model Resistor
footprint 0805_HV (0805 with 30mil clearance between pads)
footprint 2010M
footprint 2010L
pins: 1, 2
